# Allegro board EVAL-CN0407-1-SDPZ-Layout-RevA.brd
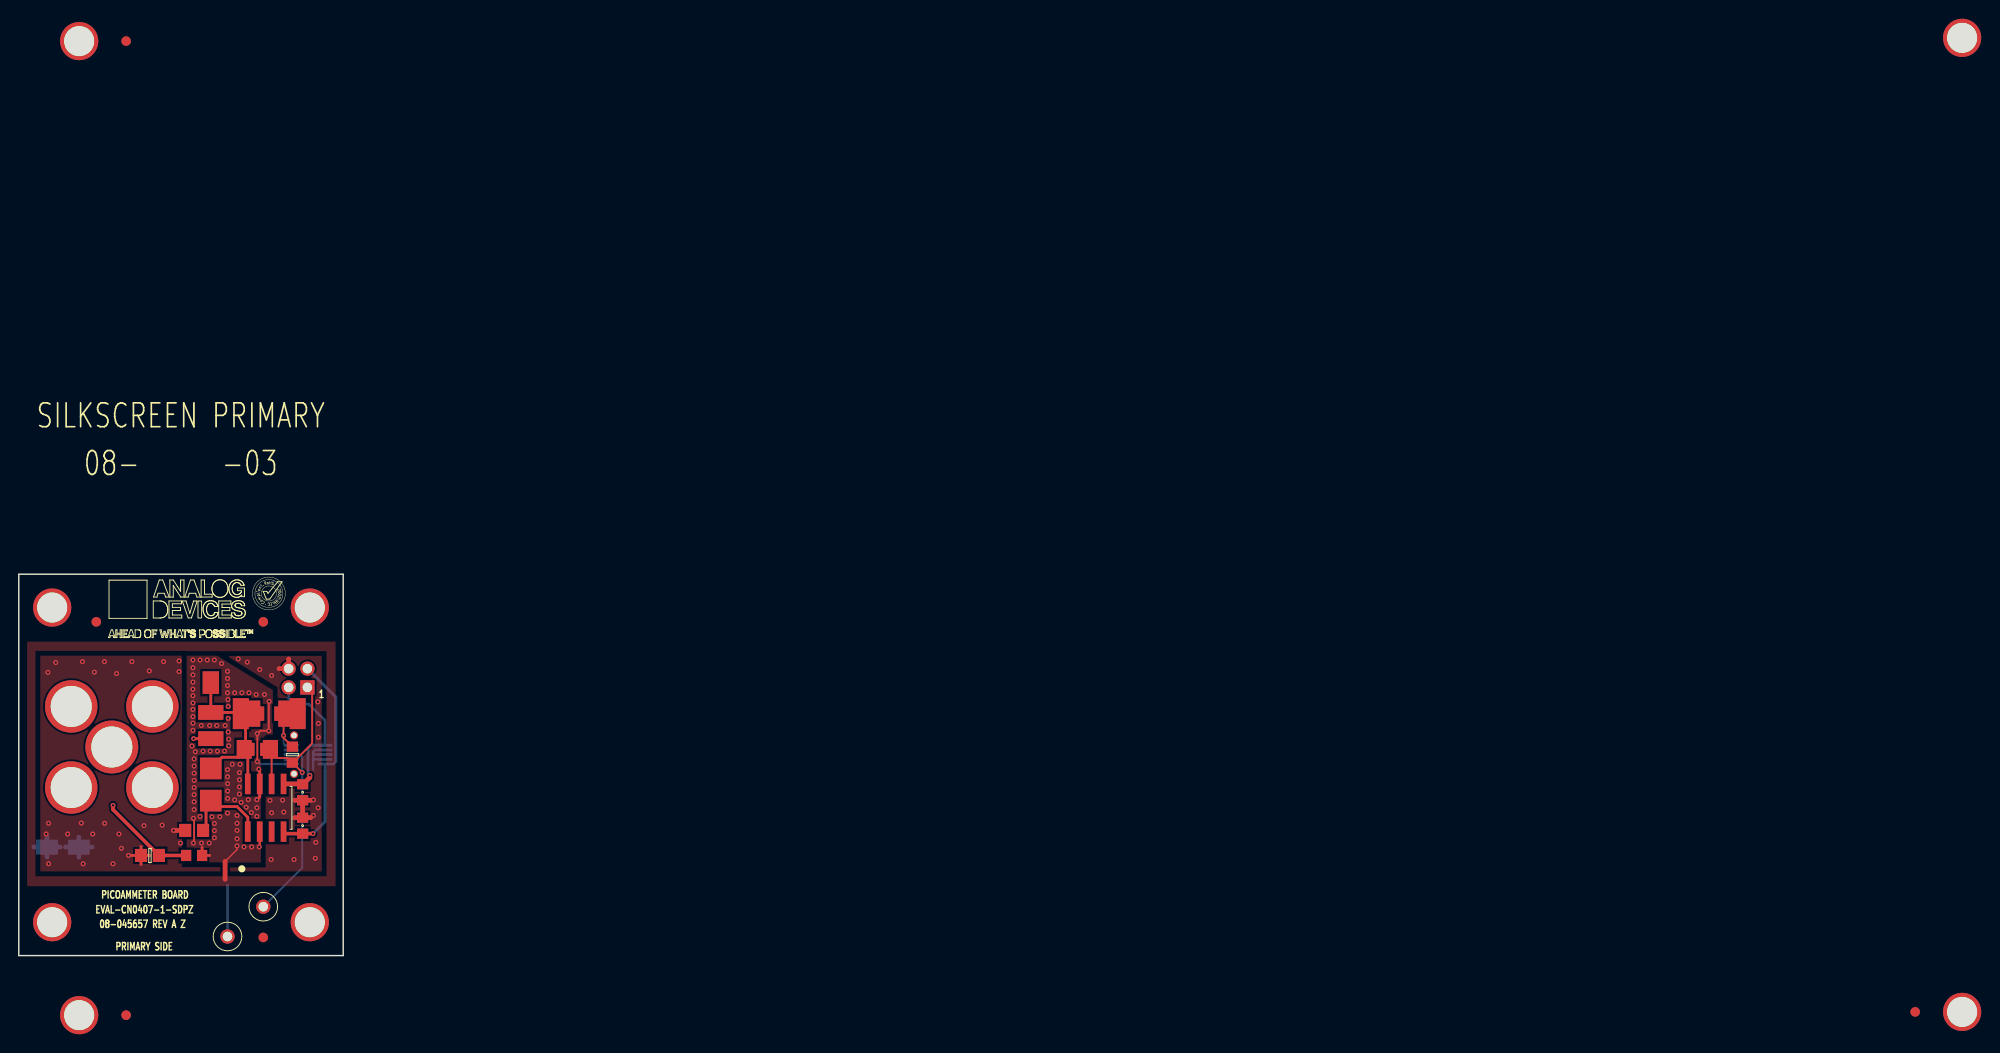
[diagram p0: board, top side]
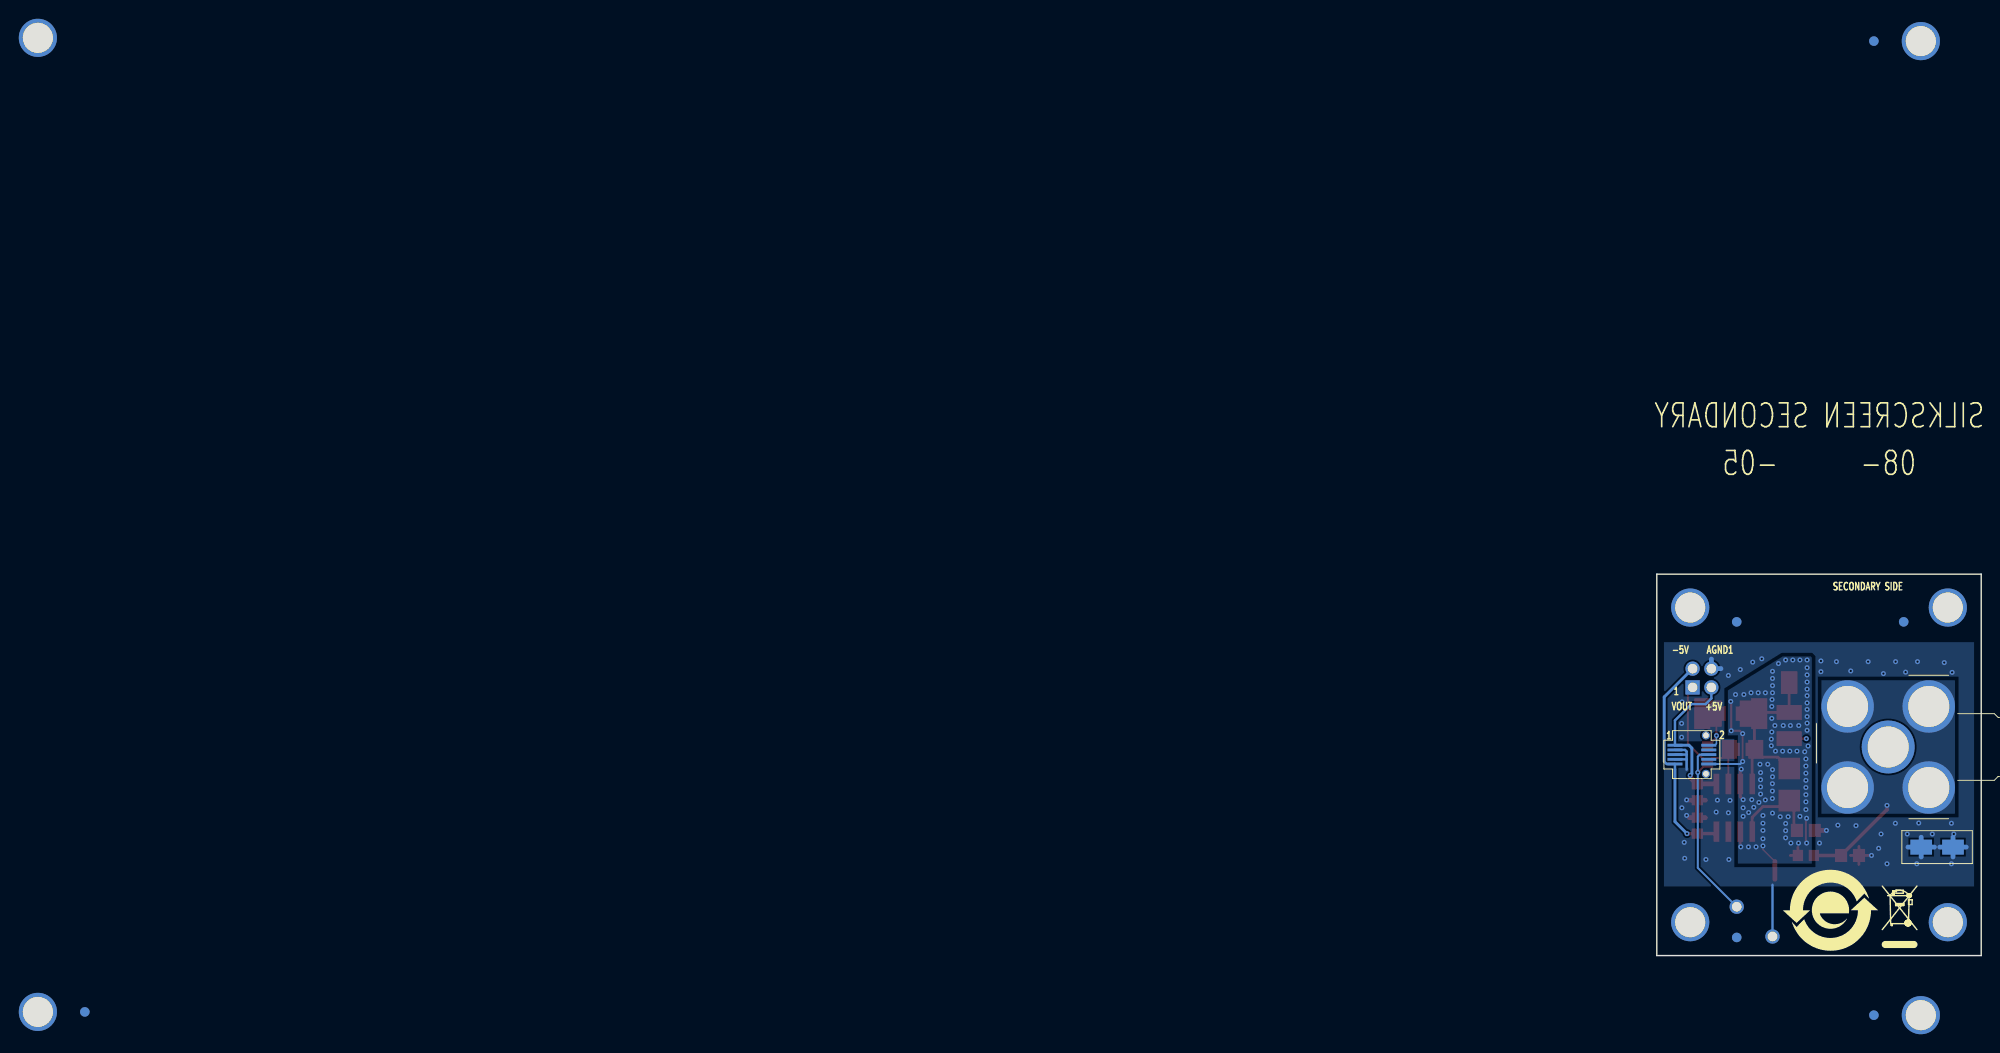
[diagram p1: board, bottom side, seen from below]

Outline 34.54 x 40.64 mm; copper layers: TOP, L2_GND, L3_POWER, BOTTOM. Coordinates in mm from the lower left corner of the outline.
Outline path: 0,40.64 0,0 34.54,0 34.54,40.64 0,40.64

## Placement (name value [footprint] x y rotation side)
C1  0.1uF  [C0603]  30.23 13.84 270 top
C2  0.1uF  [C0603]  30.23 17.4 270 top
C3  C0805_R1206_COMBO  [C0805_1206]  25.4 21.97 0 top
GND  BLK  [CNKEY5001TP]  22.23 2.03 0 top
J1  HRM-310S(40)  [CNSMARAL735W500H522]  9.91 22.23 180 bottom
J2  87758-0416  [CNHDR2X2H234]  30.73 28.57 180 top
J5  009296001202906  [CNAVX009296001202]  4.7 11.56 270 bottom
NOREF  -  []  -2.35 207.45 0 top
NOREF#2  -  []  156.37 161.28 0 top
NOREF#3  -  []  104.14 -1.27 0 top
NOREF#4  -  []  0 -2.54 0 top
NOREF#5  -  []  124.22 102.19 0 top
NOREF#6  -  []  12.01 98.25 0 top
NOREF#7  -  []  43.05 13.91 0 top
NOREF#8  -  []  178.82 -10.16 0 top
NOREF#9  -  [unnamed#2]  3.56 3.56 0 top
NOREF#10  -  []  176.28 -2.54 0 top
NOREF#11  -  []  0 91.44 0 top
NOREF#12  -  []  32.38 -74.3 0 top
NOREF#13  -  []  0 101.6 0 top
NOREF#14  -  []  64.52 -1.27 0 top
NOREF#15  -  []  16.51 31.11 0 top
NOREF#16  -  []  6.43 -6.35 0 top
NOREF#17  -  []  37.08 -2.54 0 top
NOREF#18  -  []  202.91 -1.27 0 top
NOREF#19  -  []  0 101.6 0 top
NOREF#20  -  []  123.95 -10.16 0 top
NOREF#21  -  []  0 43.18 0 top
NOREF#22  -  []  -253.87 184.53 0 top
NOREF#23  -  []  131.57 -2.54 0 top
NOREF#24  -  []  148.84 -1.27 0 top
NOREF#25  -  []  126.49 -2.54 0 top
NOREF#26  -  []  0 91.44 0 top
NOREF#27  -  []  -148.21 -204.57 0 top
NOREF#28  -  []  4.39 29.74 0 top
NOREF#29  -  []  201.93 -6 0 top
NOREF#30  -  []  168.66 -10.16 0 top
NOREF#31  -  []  59.44 -1.27 0 top
NOREF#32  -  []  10.45 49.53 0 top
NOREF#33  -  [unnamed#2]  3.56 37.08 0 top
NOREF#34  -  []  177.55 12.7 0 top
NOREF#35  -  []  -136.35 64.77 0 top
NOREF#36  -  [unnamed#2]  26.04 1.93 0 top
NOREF#37  -  []  109.22 -1.27 0 top
NOREF#38  -  []  -147.4 -203.76 0 top
NOREF#39  -  []  42.16 -2.54 0 top
NOREF#40  -  []  177.55 63.5 0 top
NOREF#41  -  []  79.25 -10.16 0 top
NOREF#42  -  [unnamed#2]  201.93 -6 0 top
NOREF#43  -  []  171.2 -2.54 0 top
NOREF#44  -  []  11.43 -6.35 0 top
NOREF#45  -  []  229.99 -58.81 0 top
NOREF#46  -  [unnamed#2]  11.43 97.44 0 top
NOREF#47  -  []  5.37 -1.27 0 top
NOREF#48  -  []  0 50.8 0 top
NOREF#49  -  []  89.41 -10.16 0 top
NOREF#50  -  []  6.43 -6.35 0 top
NOREF#51  -  []  213.36 -10.16 90 top
NOREF#52  -  []  86.87 -2.54 0 top
NOREF#53  -  []  153.92 -1.27 0 top
NOREF#54  -  [unnamed#2]  206.93 -6 0 top
NOREF#55  -  []  81.79 -2.54 0 top
NOREF#56  -  []  0 -10.16 0 top
NOREF#57  -  [unnamed#2]  206.93 97.79 0 top
NOREF#58  -  [unnamed#2]  11.43 -6.35 0 top
NOREF#59  -  []  0 93.98 0 top
NOREF#60  -  []  0 -10.16 0 top
NOREF#61  -  []  0 48.26 0 top
NOREF#62  -  []  151.72 1.14 0 top
NOREF#63  -  []  206.93 -6 0 top
NOREF#64  -  []  168.66 14.59 0 top
NOREF#65  -  []  5.37 49.53 0 top
NOREF#66  -  []  177.55 17.78 0 top
NOREF#67  -  []  207.99 -1.27 0 top
NOREF#68  -  []  134.11 -10.16 0 top
NOREF#69  -  []  10.45 -1.27 0 top
NOREF#70  -  []  0 40.64 0 top
NOREF#71  -  []  34.54 -10.16 0 top
NOREF#72  -  []  213.36 -10.16 0 top
NOREF#73  -  [unnamed#2]  30.99 37.08 0 top
NOREF#74  -  []  -39.6 115.26 0 top
NOREF#75  -  []  134.83 14.99 0 top
NOREF#76  -  [unnamed#2]  26.04 35.56 0 top
NOREF#77  -  []  44.7 -10.16 0 top
NOREF#78  -  []  177.55 68.58 0 top
NOREF#79  -  []  -399.93 -262.01 0 top
NOREF#80  -  []  6.99 98.93 0 top
NOREF#81  -  [unnamed#2]  30.99 3.56 0 top
NOREF#82  -  []  0 0 0 top
NOREF#83  -  [unnamed#2]  6.43 -6.35 0 top
NOREF#84  -  [unnamed#2]  8.26 35.56 0 top
NOREF#85  -  []  151.34 40.01 0 top
NOREF#86  -  [unnamed#2]  6.43 97.44 0 top
NOREF#87  -  []  0 0 90 top
NOREF#88  -  [unnamed#2]  26.04 35.56 180 bottom
NOREF#89  -  [unnamed#2]  8.26 35.56 180 bottom
NOREF#90  -  [unnamed#2]  26.04 1.93 180 bottom
NOREF#91  -  [unnamed#2]  11.43 97.44 180 bottom
NOREF#92  -  []  16.05 4.83 180 bottom
NOREF#93  -  []  8.89 0.86 180 bottom
NOREF#94  -  [unnamed#2]  11.43 -6.35 180 bottom
NOREF#95  -  [unnamed#2]  201.93 -6 180 bottom
P2  3907-0-18-80-30-84-10-0  [CNMILLMAX3907]  20.45 29.08 180 top
P4  DF12A(3.0)-10DS-0.5V(81)  [CNHRS-DF12A_3-10DS-05V]  30.81 21.41 270 bottom
R1  0  [R0805]  18.67 13.34 0 top
R2  TBD  [R0805_1210_2512]  26.67 25.78 0 top
R3  0  [R1210]  20.45 24.51 90 top
R4  0  [R0603]  18.67 10.67 0 top
R5  0  [R0805]  13.97 10.67 0 top
R6  0  [R0603]  29.13 21.41 270 top
U1  ADA4530-1  [SO8]  26.29 15.75 0 top
UNK+IN  5015  [CNKEY5015TP]  20.45 16.51 180 top
UNK-IN  5015  [CNKEY5015TP]  20.45 19.94 0 top
VOUT  RED  [CNKEY5001TP]  26.04 5.21 0 top

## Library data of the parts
C1 C2 = CAP: Tolerance: 5; User Part Number: UPN; alternate symbols: (); part number: CAP_SM-0.1UF,50V,5,E020065,C0603; tolerance: 5
C3 = CAP: Tolerance: N/A; User Part Number: UPN; alternate symbols: (); part number: CAP_SM-C0805_R1206_COMBO,N/A,N/A,E028187,C0805_1206; tolerance: N/A
GND = CNTP1P: Tolerance: N/A; User Part Number: UPN; alternate symbols: (); part number: CNTP1P_TH-BLK,E005347,CNKEY5001TP; tolerance: N/A
J1 = CN4PGND: User Part Number: UPN; Tolerance: N/A; alternate symbols: (); part number: CN4PGND_TH-HRM-310S(40),E028145,CNSMARAL735W500H522; tolerance: N/A
J2 = CN4P_AB: Tolerance: N/A; User Part Number: UPN; alternate symbols: (); part number: CN4P_AB_TH-87758-0416,E023708,CNHDR2X2H234; tolerance: N/A
J5 = CN2P_AB: User Part Number: UPN; Tolerance: N/A; alternate symbols: (); part number: CN2P_AB_SM-009296001202906,E027977,CNAVX009296001202; tolerance: N/A
P2 = CN1P: User Part Number: UPN; Tolerance: N/A; alternate symbols: (); part number: CN1P_SM-3907-0-18-80-30-84-10-0,E025840,CNMILLMAX3907; tolerance: N/A
P4 = CN10P_ODD_EVEN: User Part Number: UPN; Tolerance: N/A; alternate symbols: (); part number: CN10P_ODD_EVEN_SM-DF12A(3.0)-10DS-0.5V(81),E023825,CNHRS-DF12A_3-10DS-05V; tolerance: N/A
R1 R5 = RES: Tolerance: N/A; User Part Number: UPN; alternate symbols: (); part number: RES_SM-0,E004152,1/10W,N/A,R0805; tolerance: N/A
R2 = RES: Tolerance: N/A; User Part Number: UPN; alternate symbols: (); part number: RES_SM-TBD,E023508,N/A,N/A,R0805_1210_2512; tolerance: N/A
R3 = RES: Tolerance: N/A; User Part Number: UPN; alternate symbols: (); part number: RES_SM-0,E018060,0.75W,N/A,R1210; tolerance: N/A
R4 = RES: Tolerance: 1; User Part Number: UPN; alternate symbols: (); part number: RES_SM-0,E004207,1/16W,1,R0603; tolerance: 1
R6 = RES: Tolerance: 1; User Part Number: UPN; alternate symbols: R0603_A; part number: RES_SM-0,E004207,1/16W,1,R0603; tolerance: 1
U1 = ADA4530_1: Tolerance: N/A; User Part Number: UPN; alternate symbols: (); part number: ADA4530_1_SM-ADA4530-1,E020085,SO8; tolerance: N/A
UNK+IN UNK-IN = CNTP1P: Tolerance: N/A; User Part Number: UPN; alternate symbols: (); part number: CNTP1P_SM-5015,E005891,CNKEY5015TP; tolerance: N/A
VOUT = CNTP1P: Tolerance: N/A; User Part Number: UPN; alternate symbols: (); part number: CNTP1P_TH-RED,E016323,CNKEY5001TP; tolerance: N/A

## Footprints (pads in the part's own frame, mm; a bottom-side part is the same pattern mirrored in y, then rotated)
C0603
  rect 1.092x1.194 smd: 1(-0.851,0) 2(0.851,0)
C0805_1206
  custom 0.476x0.476 smd: 1(-1.25,0) 2(1.25,0)
CNAVX009296001202
  rect 1.6x2.311 smd: 1A(0,-1.694) 1B(0,1.694)
CNHDR2X2H234
  round 1.524 hole 1.016: 1A(0,-2) 2A(2,-2) 2B(2,0)
  rect 1.524x1.524 hole 1.016: 1B(0,0)
CNHRS-DF12A_3-10DS-05V
  round 0.864 hole 0.61 unplated: (-2.05,1.5) (2.05,1.5)
  rect 0.305x1.6 smd: 1(-1,-1.8) 2(-1,1.8) 3(-0.5,-1.8) 4(-0.5,1.8) 5(0,-1.8) 6(0,1.8) 7(0.5,-1.8) 8(0.5,1.8) 9(1,-1.8) 10(1,1.8)
CNKEY5001TP
  round 1.524 hole 1.016: 1(0,0)
CNKEY5015TP
  rect 2.311x2.311 smd: 1(0,0)
CNMILLMAX3907
  rect 1.753x2.413 smd: 1(0,0)
CNSMARAL735W500H522
  round 5.639 hole 4.369 unplated: (0,0)
  round 5.588 hole 4.369: 1(-4.32,-4.32) 2(4.32,-4.32) 3(4.32,4.32) 4(-4.32,4.32)
R0603
  rect 1.092x1.194 smd: 1(-0.851,0) 2(0.851,0)
R0805
  rect 1.295x1.397 smd: 1(-0.953,0) 2(0.953,0)
R0805_1210_2512
  custom 0.826x0.826 smd: 1(-2.205,0) 2(2.205,0)
R1210
  rect 1.575x2.692 smd: 1(-1.397,0) 2(1.397,0)
SO8
  rect 0.61x2.184 smd: 1(-1.905,-2.54) 2(-0.635,-2.54) 3(0.635,-2.54) 4(1.905,-2.54) 5(1.905,2.54) 6(0.635,2.54) 7(-0.635,2.54) 8(-1.905,2.54)
unnamed#2
  round 4.064 hole 3.2 unplated: (0,0)

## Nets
+5V: C2.1(N1) J2.2B(N4) P4.1(N1) U1.5(V+)
-5V: C1.2(N2) J2.1A(N1) P4.9(N5) U1.4(V-)
AGND1: C1.1(N1) C2.2(N2) GND.1(N1) J2.2A(N3) J5.1A(N1) J5.1B(N2) P4.3(N2) P4.5(N3) P4.7(N4) R1.1(N1) R3.1(N1) R5.1(N1)
MEZ_VGUARD: P4.10(N5) R4.2(N2) U1.2(GRD_1) U1.7(GRD_2)
MEZ_VOUT: C3.2(N2) J2.1B(N2) P4.6(N3) R6.2(N2) U1.6(OUT) VOUT.1(N1)
MEZ_VOUTSENSE: P4.2(N1) R2.2(N2) R6.1(N1)
UNNAMED_4_ADA45301_I1_IN: R1.2(N2) U1.1(IN+) UNK+IN.1
UNNAMED_4_ADA45301_I1_IN_1: C3.1(N1) P2.1(N1) R2.1(N1) R3.2(N2) U1.8(IN-) UNK-IN.1
UNNAMED_4_RES_I4_N2: J1.1(GND1) J1.2(GND2) J1.3(GND3) J1.4(GND4) R4.1(N1) R5.2(N2)

Pads without a net: P4 4 8; U1 3

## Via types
v1: diameter 0.533, hole 0.254, TOP to BOTTOM, 142 vias

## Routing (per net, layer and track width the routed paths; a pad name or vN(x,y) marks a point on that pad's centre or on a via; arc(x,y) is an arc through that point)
+5V: length 16.9
  TOP w0.508: v1(30.99,19.2) 30.99,18.97 30.26,18.25 C2.1 30.19,18.29 U1.5
  BOTTOM w0.254: P4.1 32.61,25.05 30.86,26.8 29.34,26.8 28.73,27.4 J2.2B
  BOTTOM w0.305: v1(30.99,19.2) 30.81,19.38 30.81,22.1 31.12,22.41 P4.1
-5V: length 23.6
  TOP w0.381: v1(31.33,12.99) C1.2 28.41,12.99 U1.4
  BOTTOM w0.254: 33.76,20.68 33.49,20.41 P4.9 32.61,19.85
  BOTTOM w0.305: 32.61,19.85 32.61,14.27 v1(31.33,12.99) ; 33.76,20.68 33.76,27.55 J2.1A
AGND1: length 38.9
  TOP w0.305: R5.1 13.92,10.67 ; R5.1 13.02,9.72 ; R5.1 v1(11.68,10.67) ; R5.1 13.02,11.62 ; v1(18.62,23.11) R3.1
  TOP w0.508: 27.72,30.58 J2.2A 28.73,31.59 ; C1.1 31.08,14.69 ; C1.1 30.23,15.49 ; C1.1 29.38,14.69 ; 29.38,16.55 C2.2 ; C2.2 30.23,15.75 ; C2.2 31.08,16.55 ; R1.1 v1(16.48,13.34)
  L3_POWER w0.508: v1(18.62,23.11) 17.21,23.11 17.14,23.18
  BOTTOM w0.254: P4.7 31.38,20.91 31.37,20.9 ; 31.37,21.41 31.37,20.9 ; 31.37,21.41 P4.5 ; 31.37,21.41 31.37,21.74 31.54,21.91 P4.3 ; 31.37,20.9 31.37,19.81 ; GND.1 22.23,7.54
  BOTTOM w0.508: 28.73,31.59 J2.2A 27.72,30.58 ; J5.1B 4.41,11.56 ; J5.1B 3,12.61 ; J5.1B 3,10.5 ; J5.1B 1.59,11.56 ; 6.39,10.5 J5.1A ; J5.1A 4.98,11.56 ; J5.1A 7.8,11.56 ; J5.1A 6.39,12.61
  vias: v1(2.92,12.95) v1(3.1,30.18) v1(3.17,14.1) v1(3.17,9.78) v1(3.94,31.22) v1(5.21,12.95) v1(6.65,14.12) v1(6.78,31.32) v1(6.86,9.78) v1(7.87,12.95) v1(8.05,30.2) v1(9.12,31.32) v1(9.14,14.1) v1(10.03,9.78) v1(10.41,30.05) v1(10.67,12.95) v1(10.92,11.43) v1(12.04,31.32) v1(13.34,13.84) v1(13.89,30.33) v1(15.27,13.89) v1(15.42,31.32) v1(17.07,31.39) v1(17.07,30.25) v1(17.22,11.99) v1(23.37,31.62) v1(24.33,31.27) v1(25.65,30.48) v1(26.75,16.54) v1(26.92,29.84) v1(26.92,15.21) v1(26.87,10.24) v1(28.09,16.56) v1(28.22,15.29) v1(29.31,10.24) v1(31.37,16.59) v1(31.37,14.94) v1(31.62,12.06) v1(31.57,10.36) v1(31.85,27.03) v1(31.9,24.74) v1(31.9,23.27) v1(31.88,15.75)
MEZ_VGUARD: length 24.7
  TOP w0.152: 18.67,14.55 v1(18.59,14.63) ; 21.97,10.03 23.24,11.3 v1(23.24,11.68) ; v1(18.59,11.99) 18.67,12.06
  TOP w0.203: v1(25.4,20.68) v1(25.4,23.65) 25.7,23.95 v1(26.62,23.95) 26.62,27.03 v1(26.67,27.08) ; 18.67,12.06 18.67,14.55
  TOP w0.254: v1(25.6,11.58) 25.65,11.63 U1.2
  TOP w0.305: v1(25.35,16.61) 25.65,16.92 U1.7 25.65,19.76 v1(25.55,19.86) ; 19.52,11.52 R4.2 20.32,10.67
  TOP w0.508: 21.97,8.13 21.97,10.03
  BOTTOM w0.203: P4.10 25.66,20.41 v1(25.4,20.68)
  vias: v1(18.44,22.33) v1(18.54,31.5) v1(18.54,30.67) v1(18.54,29.91) v1(18.54,29.15) v1(18.54,28.38) v1(18.54,27.69) v1(18.54,26.92) v1(18.54,26.23) v1(18.54,25.46) v1(18.54,24.77) v1(18.54,24) v1(18.67,20.95) v1(18.67,20.19) v1(18.67,19.43) v1(18.67,18.67) v1(18.67,17.91) v1(18.67,17.14) v1(18.67,16.38) v1(18.67,15.56) v1(18.8,21.72) v1(19.3,31.5) v1(19.3,14.83) v1(19.43,24.51) v1(19.46,11.99) v1(19.62,21.78) v1(20.07,31.5) v1(20.32,24.51) v1(20.27,11.99) v1(20.38,21.78) v1(20.56,14.8) v1(20.83,31.5) v1(20.83,14.07) v1(20.83,13.31) v1(20.83,12.55) v1(21.08,24.51) v1(21.15,21.78) v1(21.4,14.8) v1(21.59,31.11) v1(21.91,21.78) v1(21.97,24.51) v1(22.23,30.29) v1(22.23,29.53) v1(22.23,28.77) v1(22.23,28) v1(22.23,19.81) v1(22.23,19.05) v1(22.24,18.31) v1(22.24,17.53) v1(22.24,16.74) v1(22.23,15.18) v1(22.28,27.28) v1(22.3,26.54) v1(22.3,25.27) v1(22.3,23.83) v1(22.35,23.06) v1(22.35,22.35) v1(22.73,20.38) v1(22.99,28) v1(22.99,16.59) v1(23.24,14.92) v1(23.24,14.1) v1(23.24,13.34) v1(23.24,12.45) v1(23.5,19.49) v1(23.5,18.73) v1(23.5,17.97) v1(23.5,17.21) v1(23.56,20.38) v1(23.75,28) v1(23.67,16.32) v1(23.98,11.58) v1(24.22,15.8) v1(24.43,16.61) v1(24.51,28) v1(24.77,15.24) v1(24.79,11.58) v1(25.27,27.81) v1(25.35,15.75) v1(25.35,14.83) v1(26.16,27.81)
MEZ_VOUT: length 36.5
  TOP w0.203: R6.2 29.2,20.56 31.24,22.61 31.24,28.07 J2.1B ; R6.2 v1(30.18,19.51) ; R6.2 28.64,21.06 27.56,21.06 C3.2 26.65,21.38 26.92,21.11 U1.6
  BOTTOM w0.203: VOUT.1 30.18,9.35 v1(30.18,19.51) 30.18,21.2 29.97,21.41 P4.6
MEZ_VOUTSENSE: length 5.9
  TOP w0.203: R2.2 28.19,25.1 v1(28.19,23.44) 28.19,23.2 R6.1
  BOTTOM w0.152: v1(28.19,23.44) 28.19,22.58 28.36,22.41 P4.2
UNNAMED_4_ADA45301_I1_IN: length 9.7
  TOP w0.305: U1.1 24.38,14.73 23.24,15.88 21.08,15.88 UNK+IN.1 19.94,16 19.94,13.65 R1.2
UNNAMED_4_ADA45301_I1_IN_1: length 19.5
  TOP w0.305: C3.1 24.15,24.66 24.47,24.97 R2.1 24.34,25.91 R3.2 P2.1 ; C3.1 23.31,21.13 21.64,21.13 UNK-IN.1 ; C3.1 24.38,21.74 U1.8
UNNAMED_4_RES_I4_N2: length 10.3
  TOP w0.381: R4.1 R5.2 10.03,15.56 v1(10.03,16)

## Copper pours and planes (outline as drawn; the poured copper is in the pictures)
AGND1 on TOP: 2.29,31.95 2.29,8.97 21.46,8.97 21.46,9.4 21.44,9.42 17.37,9.42 17.37,31.95
AGND1 on TOP: 22.48,8.97 22.48,9.4 26.29,9.4 26.29,16.97 28.5,16.97 28.5,20.9 26.7,20.9 26.7,17.25 26.29,17.25 26.29,22.73 26.59,23.04 27.56,23.04 27.56,28.57 22.12,31.93 32.26,31.93 32.26,8.97 ; 5 cut-outs
AGND1 on BOTTOM: 0.76,33.4 0.76,7.37 33.78,7.37 33.78,33.4 ; 2 cut-outs
AGND1 on L2_GND: 0.64,0.64 0.64,40 33.91,40 33.91,0.64 ; 1 cut-out
AGND1 on L3_POWER: 0.64,0.64 0.64,40 33.91,40 33.91,0.64 ; 1 cut-out
MEZ_VGUARD on TOP: 0.89,33.45 0.89,7.39 33.73,7.39 33.73,33.45 ; 5 cut-outs
MEZ_VGUARD on BOTTOM: 21.13,31.88 26.97,28.25 26.97,23.47 25.91,23.47 25.91,9.8 18.03,9.8 18.03,31.75 18.16,31.88
MEZ_VGUARD on L2_GND: 18.19,10.05 18.05,10.19 18.05,31.81 20.97,31.81 26.89,28.12 26.89,23.66 26.18,23.66 25.77,23.25 25.77,10.05
MEZ_VGUARD on L3_POWER: 18.19,10.05 18.05,10.19 18.05,22.42 18.98,22.42 19.37,22.8 19.37,23.47 18.93,23.91 18.07,23.91 18.07,31.81 20.97,31.81 26.89,28.12 26.89,23.66 26.18,23.66 25.77,23.25 25.77,10.05
UNNAMED_4_RES_I4_N2 on BOTTOM: 17.02,15.11 17.02,29.34 2.79,29.34 2.79,15.11

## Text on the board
Ref Des/Silkscreen Bottom: SECONDARY SIDE | AGND1 | +5V
User.Comments: 6.    R2 AND C3 ARE DESIGNED TO ACCOMMODATE MULTIPLE FOOTPRINT PACKAGES. | 7.    KFS2-M2.5 PEM NUTS (M000232) MUST BE PRESSED FIT ON PRIMARY SIDE. | SEE DETAIL BELOW: | 8.    HRM-310S SMA CONNECTOR-E028145 (J1) MUST BE MOUNTED USING M2.5 PAN HEAD SCREWS | (M027987) ON SECONDARY SIDE. | 9.    CUT WIRE AWG#26 (M028423) 0.75 INCHES LONG. SOLDER ONE END TO J1 PIN AND SOLDER | OTHER END ON -IN PIN AS SHOW ON DETAIL BELOW: | 10.   BOARD TO BE MATED WITH BR-045416 - EVAL-CN0407-2-SDPZ  DATA ACQUISITION BOARD | SECONDARY SIDE | PRIMARY SIDE | J1
Ref Des/Silkscreen Top: 08-045657 REV A Z | PRIMARY SIDE | EVAL-CN0407-1-SDPZ | PICOAMMETER BOARD
DIMENSION: .062 | 30.0 | .021 | SCORE DETAIL | BOTH SIDES | +/-.003 | " " | (REF) | DIA MAX | +2/-0
PAGE_OUTLINE: N/A | 15FEB17 | CUSTOMER EVALUATION Z
User.11: SEE NOTE#7 | (4 PLACES) | SEE NOTE#9 | SEE NOTE#8
User.15: ROHS COMPLIANCE NOTE: | HOMOGENOUS MATERIALS IN THIS BOARD SHALL BE COMPLIANT | THE EU RoHS DIRECTIVE 2002/95/EC | 8MILS ROGERS 4350B | ISOLA 370HR
User.17: 08-      -07 | L2 GND
User.18: L3 POWER | 08-      -08
User.45: WIRING DETAIL | SCALE:NONE | FIGURE | SIZE | 10.0 | 40.0 | 172.0 | 24.0 | 126.0 | PLATED | NON-PLATED | FINISHED HOLES IN MILS | ALL UNITS ARE IN MILS | QTY | 142 | 6 | 4 | 2 | 8 | 1 | TOLERANCE/NOTES
